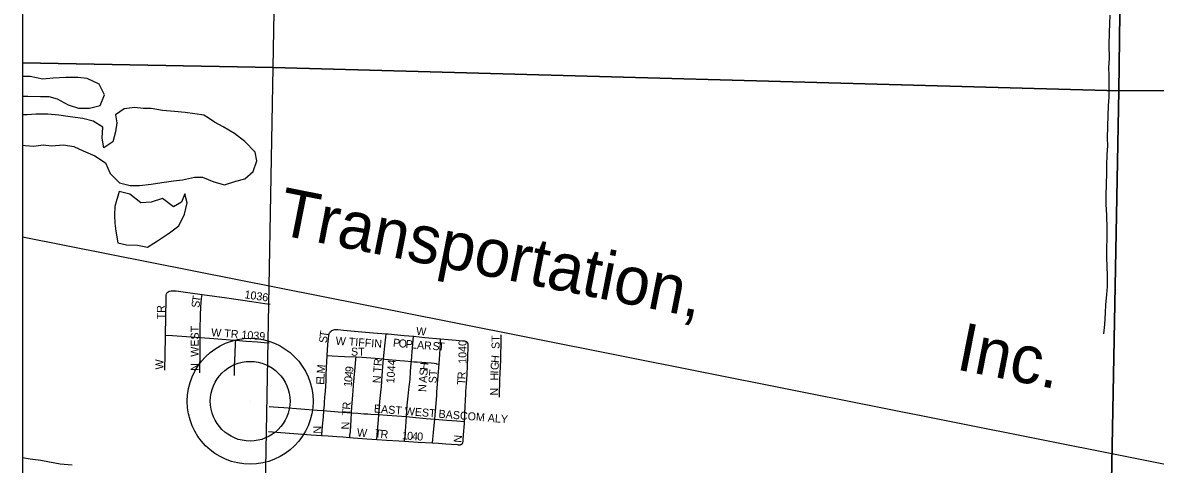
# Model space of a CAD drawing. Extents: x 1772825 to 1773716, y 1138558 to 1139032.
# Drawn here: x 1772825.358 to 1772826.028, y 1138562.918 to 1138563.179 of the extents above; entities that cross this region are included whole.
import ezdxf

# ---------------------------------------------------------------- set-up
doc = ezdxf.new("R2010")
doc.units = 0
for name, color, linetype in [('GM_X_Minor_Lake', 7, 'Continuous'), ('GM_X_Minor_River', 7, 'Continuous'), ('GM_X_Rail_Line', 7, 'Continuous'), ('GM_X_Rail_Line_Text', 7, 'Continuous'), ('GM_X_Section', 7, 'Continuous'), ('GM_X_Township', 7, 'Continuous'), ('GM_X_Township_Subdivision', 7, 'Continuous'), ('GM_X_Township_Subdivision_Text', 7, 'Continuous'), ('GM_X_Unincorporated', 7, 'Continuous'), ('GM_X_Unincorporated_Location', 7, 'Continuous')]:
    doc.layers.add(name, color=color, linetype=linetype)

msp = doc.modelspace()

# ---------------------------------------------------------------- linework, layer by layer
at = {"layer": 'GM_X_Minor_Lake'}
for points in [[(1772825.36235, 1138563.14675), (1772825.35791, 1138563.14692)], [(1772825.35791, 1138563.1352), (1772825.36097, 1138563.13518), (1772825.36855, 1138563.13496), (1772825.37347, 1138563.13493), (1772825.37839, 1138563.13358), (1772825.38482, 1138563.13014), (1772825.39088, 1138563.12821), (1772825.39751, 1138563.12818), (1772825.40377, 1138563.12967), (1772825.40626, 1138563.1361), (1772825.40325, 1138563.14238), (1772825.39607, 1138563.14564), (1772825.39058, 1138563.14623), (1772825.38338, 1138563.14627), (1772825.37598, 1138563.14592), (1772825.36992, 1138563.14519), (1772825.36235, 1138563.14675)], [(1772825.46768, 1138563.12235), (1772825.46514, 1138563.12406), (1772825.45965, 1138563.12485), (1772825.45397, 1138563.12563), (1772825.44771, 1138563.12623), (1772825.44071, 1138563.12683), (1772825.43389, 1138563.12801), (1772825.42915, 1138563.12784), (1772825.42423, 1138563.12843), (1772825.41797, 1138563.1277), (1772825.41284, 1138563.12412), (1772825.41358, 1138563.11938), (1772825.4128, 1138563.11407), (1772825.41126, 1138563.10819), (1772825.40594, 1138563.10462), (1772825.40501, 1138563.11031), (1772825.40542, 1138563.11695), (1772825.39956, 1138563.12039), (1772825.3935, 1138563.12194), (1772825.38593, 1138563.12292), (1772825.3793, 1138563.1239), (1772825.37286, 1138563.1245), (1772825.36566, 1138563.12454), (1772825.36054, 1138563.12418), (1772825.35791, 1138563.12412)], [(1772825.35791, 1138563.10619), (1772825.35933, 1138563.10598), (1772825.36444, 1138563.10576), (1772825.37013, 1138563.10649), (1772825.37506, 1138563.1059), (1772825.38207, 1138563.10644), (1772825.38813, 1138563.10546), (1772825.39361, 1138563.10297), (1772825.40061, 1138563.0999), (1772825.40685, 1138563.09589), (1772825.40966, 1138563.08961), (1772825.41513, 1138563.08409), (1772825.42157, 1138563.08235), (1772825.42706, 1138563.08251), (1772825.43389, 1138563.08324), (1772825.44015, 1138563.08416), (1772825.44716, 1138563.08526), (1772825.45247, 1138563.0858), (1772825.45949, 1138563.08729), (1772825.46422, 1138563.08727), (1772825.47103, 1138563.08458), (1772825.47728, 1138563.08284), (1772825.48392, 1138563.0849), (1772825.48923, 1138563.08639), (1772825.49418, 1138563.09073), (1772825.49648, 1138563.09698), (1772825.49536, 1138563.1021), (1772825.48933, 1138563.10839), (1772825.48328, 1138563.11316), (1772825.47648, 1138563.11718), (1772825.47137, 1138563.11986), (1772825.46768, 1138563.12235)], [(1772825.41492, 1138563.07878), (1772825.41242, 1138563.07006), (1772825.41221, 1138563.06494), (1772825.41238, 1138563.0602), (1772825.41293, 1138563.05545), (1772825.41422, 1138563.04862), (1772825.41933, 1138563.04726), (1772825.42578, 1138563.04723), (1772825.43165, 1138563.04607), (1772825.43558, 1138563.04838)], [(1772825.43558, 1138563.04838), (1772825.43773, 1138563.04964), (1772825.44476, 1138563.05454), (1772825.45027, 1138563.0585), (1772825.45371, 1138563.0655), (1772825.45525, 1138563.07213), (1772825.45376, 1138563.07745), (1772825.45184, 1138563.07253), (1772825.4471, 1138563.06989), (1772825.44067, 1138563.07467), (1772825.43384, 1138563.07261), (1772825.42778, 1138563.07226), (1772825.42136, 1138563.07723), (1772825.41492, 1138563.07878)]]:
    msp.add_lwpolyline(points, dxfattribs=at)
at = {"layer": 'GM_X_Minor_River'}
for points in [[(1772826.00087, 1138563.18316), (1772826.00044, 1138563.17292), (1772826.00022, 1138563.16552), (1772826.00038, 1138563.15755)], [(1772826.00038, 1138563.15755), (1772826.00017, 1138563.15224), (1772826.00034, 1138563.1475), (1772826.00028, 1138563.1346), (1772825.99988, 1138563.12948), (1772825.99967, 1138563.12379), (1772825.99923, 1138563.11051), (1772825.9994, 1138563.10577), (1772825.99919, 1138563.10065), (1772825.99897, 1138563.09401), (1772825.99895, 1138563.08927), (1772825.99874, 1138563.08358), (1772825.99852, 1138563.07637), (1772825.99849, 1138563.07125), (1772825.99885, 1138563.06518), (1772825.999, 1138563.05683), (1772825.99893, 1138563.03995), (1772825.9991, 1138563.03483), (1772825.99926, 1138563.02894), (1772825.99923, 1138563.02269), (1772825.99884, 1138563.01794), (1772825.99824, 1138563.01188), (1772825.99803, 1138563.00714), (1772825.99762, 1138563.00031), (1772825.99722, 1138562.99481)], [(1772825.35791, 1138562.92169), (1772825.36233, 1138562.92082), (1772825.36858, 1138562.92003), (1772825.37388, 1138562.91906), (1772825.38013, 1138562.91789), (1772825.38714, 1138562.91729)]]:
    msp.add_lwpolyline(points, dxfattribs=at)
at = {"layer": 'GM_X_Rail_Line'}
msp.add_lwpolyline([(1772825.35791, 1138563.05207), (1772825.61021, 1138563.00197), (1772826.00893, 1138562.92273), (1772826.42335, 1138562.83981), (1772826.74565, 1138562.77515), (1772827.28819, 1138562.66904), (1772827.66667, 1138562.59358), (1772827.92573, 1138562.54123), (1772827.99116, 1138562.52946), (1772828.02, 1138562.52521), (1772828.07408, 1138562.51689), (1772828.14543, 1138562.50583), (1772828.16182, 1138562.50319)], dxfattribs=at)
at = {"layer": 'GM_X_Section'}
for p, q in [((1772825.35791, 1138563.65686), (1772825.35791, 1138563.15498)), ((1772825.35791, 1138563.15498), (1772825.35791, 1138562.64747))]:
    msp.add_line(p, q, dxfattribs=at)
for points in [[(1772825.35791, 1138563.15498), (1772825.50612, 1138563.15213), (1772825.51518, 1138563.65396), (1772825.35791, 1138563.65686)], [(1772825.35791, 1138562.64747), (1772825.49688, 1138562.64649), (1772825.50612, 1138563.15213), (1772825.35791, 1138563.15498)]]:
    msp.add_lwpolyline(points, dxfattribs=at)
for points in [[(1772825.51518, 1138563.65396), (1772826.01279, 1138563.64058), (1772826.00619, 1138563.13835), (1772825.50612, 1138563.15213)], [(1772826.01279, 1138563.64058), (1772826.49778, 1138563.64814), (1772826.50172, 1138563.14184), (1772826.00619, 1138563.13835)], [(1772826.00619, 1138563.13835), (1772825.99677, 1138562.63482), (1772825.49688, 1138562.64649), (1772825.50612, 1138563.15213)], [(1772826.50172, 1138563.14184), (1772826.49968, 1138562.63999), (1772825.99677, 1138562.63482), (1772826.00619, 1138563.13835)]]:
    msp.add_lwpolyline(points, close=True, dxfattribs=at)
at = {"layer": 'GM_X_Township'}
msp.add_line((1772825.35791, 1138564.139), (1772825.35791, 1138561.13797), dxfattribs=at)
at = {"layer": 'GM_X_Township_Subdivision'}
for points in [[(1772825.44279, 1138563.01547), (1772825.44283, 1138563.01757), (1772825.44301, 1138563.0184), (1772825.44332, 1138563.01911), (1772825.44394, 1138563.01964), (1772825.4446, 1138563.01995), (1772825.4457, 1138563.02017), (1772825.44685, 1138563.02026), (1772825.44865, 1138563.02017), (1772825.45702, 1138563.01899), (1772825.46408, 1138563.018)], [(1772825.4629, 1138562.99257), (1772825.46291, 1138562.99737), (1772825.46315, 1138563.00591), (1772825.46337, 1138563.01054), (1772825.46354, 1138563.01331), (1772825.46376, 1138563.01561), (1772825.46408, 1138563.018)], [(1772825.46408, 1138563.018), (1772825.47868, 1138563.01594), (1772825.49339, 1138563.01387), (1772825.50117, 1138563.01277), (1772825.50422, 1138563.01234)], [(1772825.44236, 1138562.99403), (1772825.44279, 1138563.01547)], [(1772825.44203, 1138562.97329), (1772825.44205, 1138562.97583), (1772825.4421, 1138562.98024), (1772825.44222, 1138562.98562), (1772825.44232, 1138562.98989), (1772825.44236, 1138562.99403)], [(1772825.44236, 1138562.99403), (1772825.44654, 1138562.99371), (1772825.45214, 1138562.99332), (1772825.45759, 1138562.99294), (1772825.4629, 1138562.99257)], [(1772825.46277, 1138562.97164), (1772825.46279, 1138562.97575), (1772825.4628, 1138562.98107), (1772825.46283, 1138562.9848), (1772825.46286, 1138562.98876), (1772825.4629, 1138562.99257)], [(1772825.4629, 1138562.99257), (1772825.46848, 1138562.99221), (1772825.47598, 1138562.99164), (1772825.48296, 1138562.99111), (1772825.48399, 1138562.99101)], [(1772825.48314, 1138562.97012), (1772825.4832, 1138562.97288), (1772825.48327, 1138562.97566), (1772825.48354, 1138562.9831), (1772825.48385, 1138562.98931), (1772825.48399, 1138562.99101)], [(1772825.48399, 1138562.99101), (1772825.49025, 1138562.99047), (1772825.49674, 1138562.98994), (1772825.50083, 1138562.9896), (1772825.50376, 1138562.98936)], [(1772825.53803, 1138562.98203), (1772825.53846, 1138562.98855), (1772825.53869, 1138562.99178), (1772825.53892, 1138562.99408), (1772825.53909, 1138562.99476), (1772825.53931, 1138562.99526), (1772825.53955, 1138562.99563), (1772825.53987, 1138562.996), (1772825.54027, 1138562.99637), (1772825.54074, 1138562.99668)], [(1772825.54074, 1138562.99668), (1772825.54128, 1138562.99697), (1772825.54186, 1138562.99721), (1772825.54246, 1138562.9973), (1772825.54291, 1138562.99735), (1772825.54344, 1138562.99735), (1772825.54437, 1138562.99728), (1772825.54767, 1138562.99701), (1772825.55848, 1138562.99604), (1772825.5653, 1138562.99543), (1772825.57285, 1138562.99481)], [(1772825.57131, 1138562.97993), (1772825.57131, 1138562.97998), (1772825.57167, 1138562.98371), (1772825.57204, 1138562.98766), (1772825.5726, 1138562.99279), (1772825.57285, 1138562.99481)], [(1772825.57285, 1138562.99481), (1772825.57412, 1138562.99471), (1772825.5835, 1138562.99386), (1772825.58905, 1138562.99331)], [(1772825.58782, 1138562.97839), (1772825.5881, 1138562.98177), (1772825.5885, 1138562.98658), (1772825.58885, 1138562.99087), (1772825.58905, 1138562.99331)], [(1772825.58905, 1138562.99331), (1772825.59584, 1138562.99264), (1772825.60508, 1138562.99181)], [(1772825.60414, 1138562.97688), (1772825.60417, 1138562.9773), (1772825.60462, 1138562.98251), (1772825.60502, 1138562.98957), (1772825.60508, 1138562.99181)], [(1772825.60508, 1138562.99181), (1772825.60956, 1138562.99141), (1772825.61428, 1138562.99101), (1772825.61798, 1138562.99071), (1772825.61919, 1138562.99058), (1772825.61978, 1138562.99045), (1772825.62033, 1138562.99021), (1772825.62081, 1138562.98984)], [(1772825.63986, 1138562.95729), (1772825.63994, 1138562.96057), (1772825.64005, 1138562.96539), (1772825.64014, 1138562.96753), (1772825.64032, 1138562.97158), (1772825.64061, 1138562.97913), (1772825.64078, 1138562.98376), (1772825.64081, 1138562.98748), (1772825.64085, 1138562.98988), (1772825.64089, 1138562.99424)], [(1772825.62001, 1138562.95902), (1772825.6201, 1138562.96068), (1772825.62041, 1138562.96549), (1772825.62072, 1138562.97079), (1772825.62095, 1138562.9758), (1772825.6212, 1138562.98094), (1772825.6214, 1138562.98727), (1772825.62139, 1138562.98809), (1772825.6214, 1138562.98837), (1772825.62137, 1138562.98874), (1772825.62127, 1138562.98917), (1772825.62111, 1138562.98951), (1772825.62081, 1138562.98984)], [(1772825.53733, 1138562.96603), (1772825.5374, 1138562.96784), (1772825.53748, 1138562.97027), (1772825.53766, 1138562.9746), (1772825.53803, 1138562.98203)], [(1772825.53803, 1138562.98203), (1772825.54105, 1138562.98184), (1772825.54817, 1138562.9814), (1772825.55505, 1138562.98112)], [(1772825.55358, 1138562.9647), (1772825.55399, 1138562.96869), (1772825.55463, 1138562.97478), (1772825.55497, 1138562.9798), (1772825.55505, 1138562.98112)], [(1772825.55505, 1138562.98112), (1772825.5587, 1138562.98097), (1772825.56642, 1138562.98036), (1772825.57131, 1138562.97993)], [(1772825.57004, 1138562.96333), (1772825.57034, 1138562.96701), (1772825.5708, 1138562.97287), (1772825.57131, 1138562.97993)], [(1772825.57131, 1138562.97993), (1772825.57217, 1138562.97986), (1772825.58105, 1138562.97901), (1772825.58382, 1138562.97876), (1772825.58782, 1138562.97839)], [(1772825.58635, 1138562.96189), (1772825.58652, 1138562.96337), (1772825.58705, 1138562.96784), (1772825.58733, 1138562.9726), (1772825.58774, 1138562.97749), (1772825.58782, 1138562.97839)], [(1772825.58782, 1138562.97839), (1772825.5893, 1138562.97826), (1772825.59115, 1138562.97812), (1772825.59392, 1138562.97792), (1772825.59546, 1138562.97781), (1772825.59637, 1138562.97773), (1772825.59944, 1138562.97753), (1772825.60126, 1138562.97735), (1772825.60239, 1138562.97715), (1772825.60267, 1138562.97711), (1772825.60414, 1138562.97688)], [(1772825.60293, 1138562.96044), (1772825.60308, 1138562.96273), (1772825.60366, 1138562.97017), (1772825.60414, 1138562.97688)], [(1772825.53605, 1138562.9494), (1772825.53633, 1138562.95288), (1772825.53651, 1138562.95529), (1772825.53656, 1138562.95618), (1772825.5367, 1138562.95787), (1772825.53679, 1138562.95878), (1772825.5372, 1138562.96357), (1772825.53729, 1138562.96478), (1772825.53733, 1138562.96603)], [(1772825.55247, 1138562.94812), (1772825.55266, 1138562.95167), (1772825.55314, 1138562.95845), (1772825.55351, 1138562.96398), (1772825.55358, 1138562.9647)], [(1772825.56857, 1138562.94712), (1772825.56921, 1138562.95473), (1772825.56994, 1138562.96208), (1772825.57004, 1138562.96333)], [(1772825.58496, 1138562.94587), (1772825.5854, 1138562.95252), (1772825.58589, 1138562.95792), (1772825.58635, 1138562.96189)], [(1772825.60161, 1138562.94437), (1772825.60208, 1138562.94912), (1772825.6028, 1138562.9584), (1772825.60293, 1138562.96044)], [(1772825.61923, 1138562.94288), (1772825.6196, 1138562.95202), (1772825.62001, 1138562.95902)], [(1772825.50364, 1138562.95178), (1772825.5063, 1138562.95158), (1772825.509, 1138562.95139), (1772825.51231, 1138562.95116), (1772825.52243, 1138562.95041), (1772825.5321, 1138562.94969), (1772825.53605, 1138562.9494)], [(1772825.53485, 1138562.93464), (1772825.5351, 1138562.93786), (1772825.53544, 1138562.94213), (1772825.53577, 1138562.9458), (1772825.53605, 1138562.9494)], [(1772825.53605, 1138562.9494), (1772825.53788, 1138562.94926), (1772825.54457, 1138562.94874), (1772825.55247, 1138562.94812)], [(1772825.55132, 1138562.93351), (1772825.5515, 1138562.93493), (1772825.55172, 1138562.93678), (1772825.55203, 1138562.94045), (1772825.55226, 1138562.94422), (1772825.55247, 1138562.94812)], [(1772825.55247, 1138562.94812), (1772825.55604, 1138562.94783), (1772825.5596, 1138562.94755), (1772825.56204, 1138562.94739), (1772825.56387, 1138562.9473), (1772825.56788, 1138562.94715), (1772825.56857, 1138562.94712)], [(1772825.56739, 1138562.93237), (1772825.5678, 1138562.93753), (1772825.56831, 1138562.94388), (1772825.56857, 1138562.94712)], [(1772825.56857, 1138562.94712), (1772825.57339, 1138562.94675), (1772825.58496, 1138562.94587)], [(1772825.58364, 1138562.93133), (1772825.58405, 1138562.93455), (1772825.58433, 1138562.93729), (1772825.58472, 1138562.94273), (1772825.58496, 1138562.94587)], [(1772825.58496, 1138562.94587), (1772825.58853, 1138562.94555), (1772825.59656, 1138562.94482), (1772825.60161, 1138562.94437)], [(1772825.60024, 1138562.93033), (1772825.60046, 1138562.93244), (1772825.60087, 1138562.93642), (1772825.60143, 1138562.94262), (1772825.60161, 1138562.94437)], [(1772825.60161, 1138562.94437), (1772825.60872, 1138562.94372), (1772825.61462, 1138562.94325), (1772825.61923, 1138562.94288)], [(1772825.61782, 1138562.92974), (1772825.61797, 1138562.92996), (1772825.61809, 1138562.93019), (1772825.61817, 1138562.93038), (1772825.61824, 1138562.9306), (1772825.61829, 1138562.93082), (1772825.61834, 1138562.93107), (1772825.61837, 1138562.93136), (1772825.6184, 1138562.93162), (1772825.61842, 1138562.93189), (1772825.61845, 1138562.93214), (1772825.61867, 1138562.93505), (1772825.61919, 1138562.94179), (1772825.61923, 1138562.94288)], [(1772825.50339, 1138562.9371), (1772825.50574, 1138562.93693), (1772825.51319, 1138562.93634), (1772825.52861, 1138562.93513), (1772825.53485, 1138562.93464)], [(1772825.53485, 1138562.93464), (1772825.53857, 1138562.9344), (1772825.54366, 1138562.93407), (1772825.54734, 1138562.93382), (1772825.55132, 1138562.93351)], [(1772825.55132, 1138562.93351), (1772825.5535, 1138562.93334), (1772825.56149, 1138562.93274), (1772825.56739, 1138562.93237)], [(1772825.56739, 1138562.93237), (1772825.57312, 1138562.93202), (1772825.58034, 1138562.93156), (1772825.58364, 1138562.93133)], [(1772825.58364, 1138562.93133), (1772825.58631, 1138562.93114), (1772825.59188, 1138562.93079), (1772825.60024, 1138562.93033)], [(1772825.60024, 1138562.93033), (1772825.6038, 1138562.93008), (1772825.60818, 1138562.92977), (1772825.61494, 1138562.92927), (1772825.6154, 1138562.92924), (1772825.61582, 1138562.92922), (1772825.61618, 1138562.92923), (1772825.61657, 1138562.92924), (1772825.61689, 1138562.92929), (1772825.61718, 1138562.92937), (1772825.6175, 1138562.92951), (1772825.61767, 1138562.92961), (1772825.61782, 1138562.92974)]]:
    msp.add_lwpolyline(points, dxfattribs=at)
at = {"layer": 'GM_X_Unincorporated'}
for radius in [0.0372, 0.02358]:
    msp.add_circle((1772825.49244, 1138562.95493), radius, dxfattribs=at)
at = {"layer": 'GM_X_Unincorporated_Location'}
msp.add_line((1772825.49244, 1138562.95493), (1772825.49244, 1138562.95493), dxfattribs=at)

# ---------------------------------------------------------------- texts
at = {"layer": 'GM_X_Rail_Line_Text'}
for s, height, rotation, p in [('Transportation,', 0.0283144, 348.75588, (1772825.50769, 1138563.05372)), ('Inc.', 0.028314, 348.82176, (1772825.90921, 1138562.97384))]:
    msp.add_text(s, height=height, rotation=rotation, dxfattribs=at).set_placement(p)
at = {"layer": 'GM_X_Township_Subdivision_Text'}
for s, height, rotation, p in [('1036', 0.004735, 351.86662, (1772825.48888, 1138563.01583)), ('TR', 0.004735, 90, (1772825.44203, 1138563.00329)), ('S', 0.00473, 85.048, (1772825.46245, 1138563.01)), ('T', 0.00473, 81.49895, (1772825.46273, 1138563.01324)), ('WEST', 0.004735, 90, (1772825.46203, 1138562.9812)), ('W TR 1039', 0.004735, 355.67103, (1772825.46926, 1138562.99334)), ('W', 0.00473, 355.58715, (1772825.59049, 1138562.99417)), ('S', 0.00473, 85.048, (1772825.53787, 1138562.98916)), ('T', 0.00473, 81.52597, (1772825.53814, 1138562.99241)), ('W TIFFIN', 0.004735, 356.18423, (1772825.54291, 1138562.98834)), ('P', 0.00473, 353.89517, (1772825.57673, 1138562.98732)), ('O', 0.00473, 354.10102, (1772825.58007, 1138562.98697)), ('P', 0.00473, 354.65448, (1772825.58426, 1138562.98653)), ('ST', 0.004735, 90, (1772825.63995, 1138562.98579)), ('ST', 0.004735, 0.00001, (1772825.55209, 1138562.98187)), ('L', 0.00473, 355.06197, (1772825.58761, 1138562.98622)), ('A', 0.00473, 355.75902, (1772825.591, 1138562.98593)), ('R', 0.00473, 356.11731, (1772825.59518, 1138562.98562)), ('S', 0.00473, 356.20207, (1772825.60018, 1138562.98528)), ('T', 0.00473, 356.17321, (1772825.60351, 1138562.98506)), ('1040', 0.004735, 90, (1772825.62038, 1138562.97704)), ('W', 0.00473, 90, (1772825.4412, 1138562.9737)), ('N TR', 0.004735, 86.3034, (1772825.56955, 1138562.96543)), ('1044', 0.004735, 85.91268, (1772825.57765, 1138562.96534)), ('H', 0.00473, 84.94409, (1772825.59749, 1138562.97314)), ('G', 0.00473, 87.76967, (1772825.63936, 1138562.9733)), ('H', 0.00473, 84.94409, (1772825.63952, 1138562.97741)), ('N', 0.00473, 90, (1772825.46203, 1138562.97287)), ('L', 0.00473, 87.26718, (1772825.53636, 1138562.9679)), ('M', 0.00473, 85.02158, (1772825.53651, 1138562.97118)), ('4', 0.00473, 83.42878, (1772825.553, 1138562.96895)), ('9', 0.00473, 83.42878, (1772825.55334, 1138562.97185)), ('S', 0.00473, 84.97349, (1772825.59719, 1138562.96982)), ('ST', 0.004735, 86.42535, (1772825.60267, 1138562.96541)), ('R', 0.00473, 86.50091, (1772825.6197, 1138562.96779)), ('H', 0.00473, 87.76967, (1772825.63912, 1138562.96706)), ('I', 0.00473, 87.77052, (1772825.63928, 1138562.97122)), ('E', 0.00473, 87.26718, (1772825.5362, 1138562.96457)), ('1', 0.00473, 85.37378, (1772825.55245, 1138562.96318)), ('0', 0.00473, 83.64946, (1772825.55268, 1138562.96605)), ('N', 0.00473, 88.09812, (1772825.59661, 1138562.96033)), ('A', 0.00473, 84.94409, (1772825.59683, 1138562.96567)), ('T', 0.00473, 87.29447, (1772825.61954, 1138562.96448)), ('N', 0.00473, 90, (1772825.63912, 1138562.95829)), ('R', 0.00473, 85.45415, (1772825.55167, 1138562.94985)), ('EAST WEST BASCOM ALY', 0.0047348, 355.34587, (1772825.56549, 1138562.94834)), ('T', 0.00473, 89.12573, (1772825.55162, 1138562.9466)), ('N', 0.00473, 90, (1772825.53453, 1138562.93579)), ('N', 0.00473, 90, (1772825.5512, 1138562.93829)), ('W', 0.00473, 355.60387, (1772825.55549, 1138562.93417)), ('T', 0.00473, 353.42745, (1772825.56595, 1138562.93375)), ('R', 0.00473, 354.60071, (1772825.56936, 1138562.93336)), ('1', 0.00473, 355.24932, (1772825.58217, 1138562.93251)), ('0', 0.00473, 355.24932, (1772825.58508, 1138562.93226)), ('4', 0.00473, 355.24932, (1772825.58799, 1138562.93202)), ('0', 0.00473, 358.29489, (1772825.59117, 1138562.93177)), ('N', 0.00473, 84.61561, (1772825.61746, 1138562.93025))]:
    msp.add_text(s, height=height, rotation=rotation, dxfattribs=at).set_placement(p)

doc.saveas('drawing.dxf')
